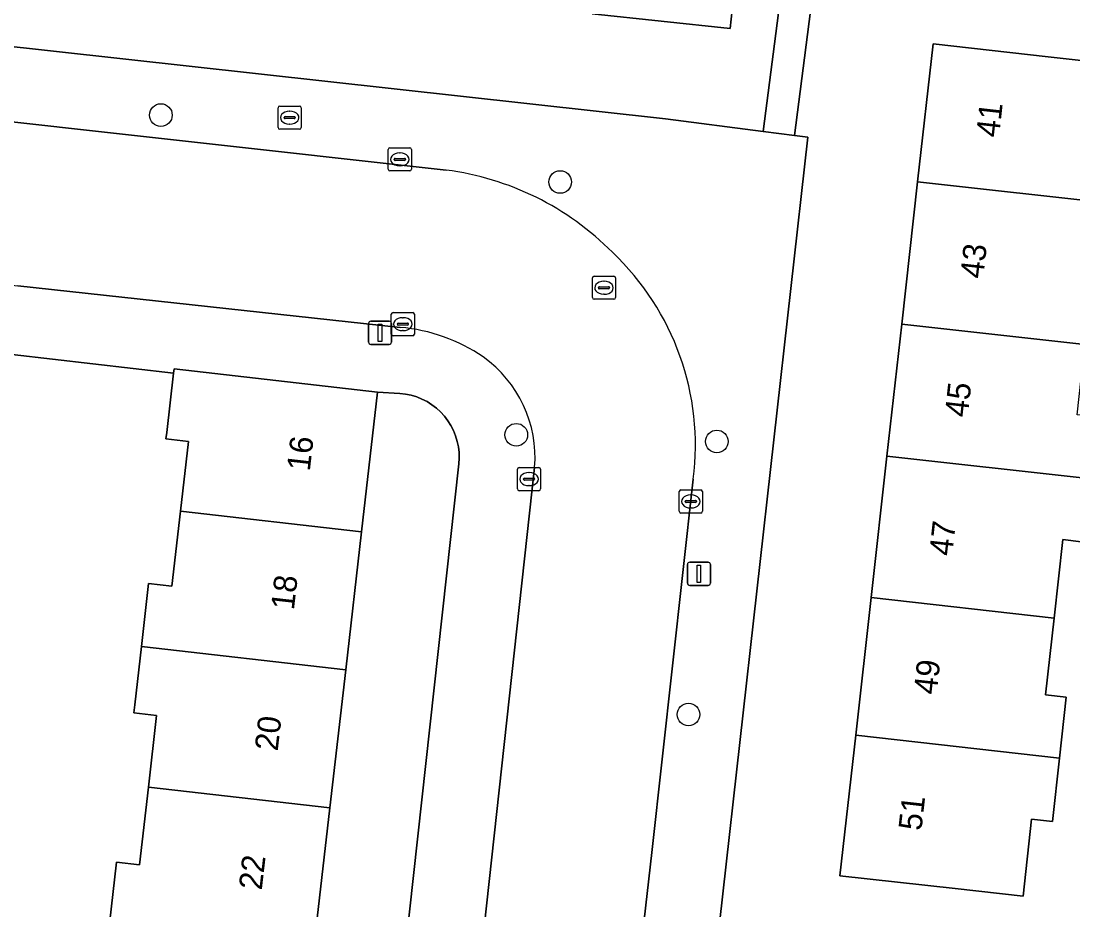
# Model space of a CAD drawing. Extents: x 162026 to 163502, y 387295 to 388169.
# Drawn here: x 162399.19 to 162444.62, y 387708.7 to 387747.09 of the extents above; entities that cross this region are included whole.
import ezdxf

# ---------------------------------------------------------------- set-up
doc = ezdxf.new("R2010")
doc.units = 0
for name, color, linetype in [('IMGEO_Boom', 7, 'Continuous'), ('IMGEO_Brandkraan', 7, 'Continuous'), ('IMGEO_Erf', 7, 'Continuous'), ('IMGEO_Kolk', 7, 'Continuous'), ('IMGEO_Lichtmast', 7, 'Continuous'), ('IMGEO_Pand', 7, 'Continuous'), ('IMGEO_Pand_nummerreeks', 7, 'Continuous'), ('IMGEO_Rijbaan_lokaal_open', 7, 'Continuous'), ('IMGEO_Rioolput', 7, 'Continuous'), ('IMGEO_Voetpad_open', 7, 'Continuous')]:
    doc.layers.add(name, color=color, linetype=linetype)

msp = doc.modelspace()

# ---------------------------------------------------------------- linework, layer by layer
at = {"layer": 'IMGEO_Boom'}
for centre in [(162405.228, 387743.028), (162422.469, 387740.137), (162420.578, 387729.22), (162429.235, 387728.932), (162428.012, 387717.135)]:
    msp.add_circle(centre, 0.489, dxfattribs=at)
at = {"layer": 'IMGEO_Brandkraan'}
for p, q in [((162410.289, 387742.49), (162410.289, 387743.342)), ((162410.364, 387743.416), (162411.216, 387743.416)), ((162410.777, 387743.196), (162410.802, 387743.196)), ((162411.29, 387743.342), (162411.29, 387742.49)), ((162410.548, 387742.91), (162410.548, 387742.922)), ((162410.986, 387742.873), (162410.588, 387742.873)), ((162410.591, 387742.959), (162410.989, 387742.959)), ((162411.032, 387742.922), (162411.032, 387742.91)), ((162411.216, 387742.416), (162410.364, 387742.416)), ((162410.8, 387742.636), (162410.775, 387742.636))]:
    msp.add_line(p, q, dxfattribs=at)
for points in [[(162410.289, 387742.49), (162410.289, 387743.342)], [(162410.364, 387743.416), (162411.216, 387743.416)], [(162411.29, 387743.342), (162411.29, 387742.49)], [(162411.216, 387742.416), (162410.364, 387742.416)]]:
    msp.add_lwpolyline(points, dxfattribs=at)
for centre, radius, start, end in [((162410.366, 387743.34), 0.0765, 91.552, 178.448), ((162410.366, 387743.34), 0.0765, 91.552, 178.448), ((162411.214, 387743.34), 0.0765, 1.552, 88.448), ((162411.214, 387743.34), 0.0765, 1.552, 88.448), ((162410.588, 387742.919), 0.0403, 85.8775, 175.7526), ((162410.585, 387742.909), 0.0366, 178.938, 274.7102), ((162410.989, 387742.916), 0.043, 264.8664, 352.4533), ((162410.993, 387742.921), 0.0386, 1.7309, 96.639), ((162410.366, 387742.492), 0.0765, 181.552, 268.448), ((162410.366, 387742.492), 0.0765, 181.552, 268.448), ((162411.214, 387742.492), 0.0765, 271.552, 358.448), ((162411.214, 387742.492), 0.0765, 271.552, 358.448)]:
    msp.add_arc(centre, radius, start, end, dxfattribs=at)
for centre, major_axis, ratio, start_param, end_param in [((162410.776, 387742.916), (-0.387, 0.002), 0.722429, 4.712389, 7.853982), ((162410.801, 387742.916), (-0.39, 0.002), 0.717154, 1.570796, 4.712389)]:
    msp.add_ellipse(centre, major_axis=major_axis, ratio=ratio, start_param=start_param, end_param=end_param, dxfattribs=at)
at = {"layer": 'IMGEO_Erf'}
for points in [[(162362.56, 387750), (162427.027, 387742.863), (162431.245, 387742.321), (162433.264, 387758.035)], [(162433.651, 387750.442), (162432.585, 387742.149), (162433.168, 387742.074), (162425.088, 387670.179)], [(162430.16, 387750), (162429.814, 387746.763), (162423.847, 387747.401)], [(162444.975, 387724.601), (162444.184, 387724.69), (162443.805, 387721.304), (162443.435, 387717.994), (162444.331, 387717.893), (162444.036, 387715.257), (162443.728, 387712.511), (162442.833, 387712.611), (162442.461, 387709.288), (162439.525, 387709.617), (162434.556, 387710.173), (162435.235, 387716.241), (162435.9, 387722.189), (162436.584, 387728.302), (162437.222, 387733.998), (162437.91, 387740.147), (162438.576, 387746.104), (162443.545, 387745.548), (162446.519, 387745.215)], [(162403.009, 387708.103), (162403.313, 387710.755), (162404.303, 387710.641), (162404.688, 387714.001), (162405.043, 387717.092), (162404.057, 387717.206), (162404.097, 387717.556), (162404.386, 387720.081), (162404.696, 387722.789), (162405.696, 387722.674), (162406.068, 387725.925), (162406.413, 387728.932), (162405.448, 387729.043), (162405.479, 387729.311), (162405.775, 387731.887), (162398.802, 387732.687)], [(162413.649, 387687.57), (162418.095, 387727.958), (162418.111, 387728.203), (162418.105, 387728.449), (162418.077, 387728.694), (162418.027, 387728.935), (162417.956, 387729.17), (162417.864, 387729.399), (162417.753, 387729.618), (162417.622, 387729.826), (162417.473, 387730.022), (162417.307, 387730.203), (162417.125, 387730.369), (162416.93, 387730.519), (162416.722, 387730.65), (162416.503, 387730.762), (162416.275, 387730.854), (162416.039, 387730.925), (162415.798, 387730.975), (162415.546, 387731.004), (162414.588, 387731.063), (162413.896, 387725.027), (162413.213, 387719.069), (162412.529, 387713.102), (162411.84, 387707.09)]]:
    msp.add_lwpolyline(points, dxfattribs=at)
at = {"layer": 'IMGEO_Kolk'}
for p, q in [((162415.046, 387740.687), (162415.046, 387741.539)), ((162415.121, 387741.613), (162415.973, 387741.613)), ((162415.534, 387741.393), (162415.559, 387741.393)), ((162416.047, 387741.539), (162416.047, 387740.687)), ((162415.305, 387741.107), (162415.305, 387741.119)), ((162415.743, 387741.07), (162415.345, 387741.07)), ((162415.348, 387741.156), (162415.746, 387741.156)), ((162415.789, 387741.119), (162415.789, 387741.107)), ((162415.973, 387740.613), (162415.121, 387740.613)), ((162415.557, 387740.833), (162415.532, 387740.833)), ((162415.179, 387733.571), (162415.179, 387734.423)), ((162415.254, 387734.497), (162416.106, 387734.497)), ((162415.667, 387734.277), (162415.692, 387734.277)), ((162416.18, 387734.423), (162416.18, 387733.571)), ((162415.438, 387733.991), (162415.438, 387734.003)), ((162415.876, 387733.954), (162415.478, 387733.954)), ((162415.481, 387734.04), (162415.879, 387734.04)), ((162415.69, 387733.717), (162415.665, 387733.717)), ((162415.922, 387734.003), (162415.922, 387733.991)), ((162416.106, 387733.497), (162415.254, 387733.497)), ((162420.627, 387726.878), (162420.627, 387727.73)), ((162420.702, 387727.804), (162421.554, 387727.804)), ((162421.628, 387727.73), (162421.628, 387726.878)), ((162420.886, 387727.298), (162420.886, 387727.31)), ((162421.324, 387727.261), (162420.926, 387727.261)), ((162420.929, 387727.347), (162421.327, 387727.347)), ((162421.115, 387727.584), (162421.14, 387727.584)), ((162421.37, 387727.31), (162421.37, 387727.298)), ((162421.554, 387726.804), (162420.702, 387726.804)), ((162421.138, 387727.024), (162421.113, 387727.024)), ((162427.689, 387726.839), (162428.541, 387726.839)), ((162427.614, 387725.913), (162427.614, 387726.765)), ((162427.873, 387726.333), (162427.873, 387726.345)), ((162427.916, 387726.382), (162428.314, 387726.382)), ((162428.102, 387726.619), (162428.127, 387726.619)), ((162428.357, 387726.345), (162428.357, 387726.333)), ((162428.615, 387726.765), (162428.615, 387725.913)), ((162428.311, 387726.296), (162427.913, 387726.296)), ((162428.125, 387726.059), (162428.1, 387726.059)), ((162428.541, 387725.839), (162427.689, 387725.839))]:
    msp.add_line(p, q, dxfattribs=at)
for points in [[(162415.046, 387740.687), (162415.046, 387741.539)], [(162415.121, 387741.613), (162415.973, 387741.613)], [(162416.047, 387741.539), (162416.047, 387740.687)], [(162415.973, 387740.613), (162415.121, 387740.613)], [(162415.179, 387733.571), (162415.179, 387734.423)], [(162415.254, 387734.497), (162416.106, 387734.497)], [(162416.18, 387734.423), (162416.18, 387733.571)], [(162416.106, 387733.497), (162415.254, 387733.497)], [(162420.627, 387726.878), (162420.627, 387727.73)], [(162420.702, 387727.804), (162421.554, 387727.804)], [(162421.628, 387727.73), (162421.628, 387726.878)], [(162421.554, 387726.804), (162420.702, 387726.804)], [(162427.689, 387726.839), (162428.541, 387726.839)], [(162427.614, 387725.913), (162427.614, 387726.765)], [(162428.615, 387726.765), (162428.615, 387725.913)], [(162428.541, 387725.839), (162427.689, 387725.839)]]:
    msp.add_lwpolyline(points, dxfattribs=at)
for centre, radius, start, end in [((162415.123, 387741.537), 0.0765, 91.552, 178.448), ((162415.123, 387741.537), 0.0765, 91.552, 178.448), ((162415.971, 387741.537), 0.0765, 1.552, 88.448), ((162415.971, 387741.537), 0.0765, 1.552, 88.448), ((162415.345, 387741.116), 0.0403, 85.8775, 175.7526), ((162415.342, 387741.106), 0.0366, 178.938, 274.7102), ((162415.746, 387741.113), 0.043, 264.8664, 352.4533), ((162415.75, 387741.118), 0.0386, 1.7309, 96.639), ((162415.123, 387740.689), 0.0765, 181.552, 268.448), ((162415.123, 387740.689), 0.0765, 181.552, 268.448), ((162415.971, 387740.689), 0.0765, 271.552, 358.448), ((162415.971, 387740.689), 0.0765, 271.552, 358.448), ((162415.256, 387734.421), 0.0765, 91.552, 178.448), ((162415.256, 387734.421), 0.0765, 91.552, 178.448), ((162416.104, 387734.421), 0.0765, 1.552, 88.448), ((162416.104, 387734.421), 0.0765, 1.552, 88.448), ((162415.478, 387734), 0.0403, 85.8775, 175.7526), ((162415.475, 387733.99), 0.0366, 178.938, 274.7102), ((162415.879, 387733.997), 0.043, 264.8664, 352.4533), ((162415.883, 387734.002), 0.0386, 1.7309, 96.639), ((162415.256, 387733.573), 0.0765, 181.552, 268.448), ((162415.256, 387733.573), 0.0765, 181.552, 268.448), ((162416.104, 387733.573), 0.0765, 271.552, 358.448), ((162416.104, 387733.573), 0.0765, 271.552, 358.448), ((162420.704, 387727.728), 0.0765, 91.552, 178.448), ((162420.704, 387727.728), 0.0765, 91.552, 178.448), ((162421.552, 387727.728), 0.0765, 1.552, 88.448), ((162421.552, 387727.728), 0.0765, 1.552, 88.448), ((162420.926, 387727.307), 0.0403, 85.8775, 175.7526), ((162420.923, 387727.297), 0.0366, 178.938, 274.7102), ((162421.327, 387727.304), 0.043, 264.8664, 352.4533), ((162421.331, 387727.309), 0.0386, 1.7309, 96.639), ((162420.704, 387726.88), 0.0765, 181.552, 268.448), ((162420.704, 387726.88), 0.0765, 181.552, 268.448), ((162421.552, 387726.88), 0.0765, 271.552, 358.448), ((162421.552, 387726.88), 0.0765, 271.552, 358.448), ((162427.691, 387726.763), 0.0765, 91.552, 178.448), ((162427.691, 387726.763), 0.0765, 91.552, 178.448), ((162428.539, 387726.763), 0.0765, 1.552, 88.448), ((162428.539, 387726.763), 0.0765, 1.552, 88.448), ((162427.913, 387726.342), 0.0403, 85.8775, 175.7526), ((162427.91, 387726.332), 0.0366, 178.938, 274.7102), ((162428.314, 387726.339), 0.043, 264.8664, 352.4533), ((162428.318, 387726.344), 0.0386, 1.7309, 96.639), ((162427.691, 387725.915), 0.0765, 181.552, 268.448), ((162427.691, 387725.915), 0.0765, 181.552, 268.448), ((162428.539, 387725.915), 0.0765, 271.552, 358.448), ((162428.539, 387725.915), 0.0765, 271.552, 358.448)]:
    msp.add_arc(centre, radius, start, end, dxfattribs=at)
for centre, major_axis, ratio, start_param, end_param in [((162415.533, 387741.113), (-0.387, 0.002), 0.722429, 4.712389, 7.853982), ((162415.558, 387741.113), (-0.39, 0.002), 0.717154, 1.570796, 4.712389), ((162415.666, 387733.997), (-0.387, 0.002), 0.722429, 4.712389, 7.853982), ((162415.691, 387733.997), (-0.39, 0.002), 0.717154, 1.570796, 4.712389), ((162421.114, 387727.304), (-0.387, 0.002), 0.722429, 4.712389, 7.853982), ((162421.139, 387727.304), (-0.39, 0.002), 0.717154, 1.570796, 4.712389), ((162428.101, 387726.339), (-0.387, 0.002), 0.722429, 4.712389, 7.853982), ((162428.126, 387726.339), (-0.39, 0.002), 0.717154, 1.570796, 4.712389)]:
    msp.add_ellipse(centre, major_axis=major_axis, ratio=ratio, start_param=start_param, end_param=end_param, dxfattribs=at)
at = {"layer": 'IMGEO_Lichtmast'}
for p, q in [((162414.297, 387734.125), (162415.087, 387734.125)), ((162415.087, 387734.125), (162414.297, 387734.125)), ((162414.197, 387733.225), (162414.197, 387734.025)), ((162414.197, 387734.025), (162414.197, 387733.225)), ((162415.187, 387734.025), (162415.187, 387733.225)), ((162415.187, 387733.225), (162415.187, 387734.025)), ((162415.087, 387733.125), (162414.297, 387733.125)), ((162414.297, 387733.125), (162415.087, 387733.125)), ((162427.968, 387722.814), (162427.968, 387723.614)), ((162427.968, 387723.614), (162427.968, 387722.814)), ((162428.068, 387723.714), (162428.858, 387723.714)), ((162428.858, 387723.714), (162428.068, 387723.714)), ((162428.958, 387723.614), (162428.958, 387722.814)), ((162428.958, 387722.814), (162428.958, 387723.614)), ((162428.858, 387722.714), (162428.068, 387722.714)), ((162428.068, 387722.714), (162428.858, 387722.714))]:
    msp.add_line(p, q, dxfattribs=at)
for points in [[(162414.617, 387734), (162414.767, 387734), (162414.767, 387733.25), (162414.617, 387733.25), (162414.617, 387734)], [(162428.388, 387723.589), (162428.538, 387723.589), (162428.538, 387722.839), (162428.388, 387722.839), (162428.388, 387723.589)]]:
    msp.add_lwpolyline(points, dxfattribs=at)
for centre, start, end in [((162414.297, 387734.025), 90, 180), ((162414.297, 387734.025), 90, 180), ((162415.087, 387734.025), 0, 90), ((162415.087, 387734.025), 360, 90), ((162414.297, 387733.225), 180, 270), ((162414.297, 387733.225), 180, 270), ((162415.087, 387733.225), 270, 0), ((162415.087, 387733.225), 270, 0), ((162428.068, 387723.614), 90, 180), ((162428.068, 387723.614), 90, 180), ((162428.858, 387723.614), 0, 90), ((162428.858, 387723.614), 360, 90), ((162428.068, 387722.814), 180, 270), ((162428.068, 387722.814), 180, 270), ((162428.858, 387722.814), 270, 0), ((162428.858, 387722.814), 270, 0)]:
    msp.add_arc(centre, 0.1, start, end, dxfattribs=at)
at = {"layer": 'IMGEO_Pand'}
for points in [[(162423.847, 387747.401), (162429.814, 387746.763), (162430.16, 387750), (162430.346, 387751.735), (162430.662, 387754.692), (162427.394, 387755.041), (162427.481, 387755.851), (162424.782, 387756.14), (162424.125, 387750)], [(162446.6, 387739.174), (162446.903, 387741.882), (162446.155, 387741.965), (162446.519, 387745.215), (162443.545, 387745.548), (162438.576, 387746.104), (162437.91, 387740.147)], [(162446.6, 387739.174), (162437.91, 387740.147), (162437.222, 387733.998), (162445.136, 387733.112), (162445.16, 387733.326), (162448.504, 387732.942), (162449.179, 387738.885)], [(162437.222, 387733.998), (162436.584, 387728.302), (162445.28, 387727.328), (162445.578, 387729.992), (162444.796, 387730.079), (162445.136, 387733.112)], [(162414.588, 387731.063), (162405.796, 387732.071), (162405.775, 387731.887), (162405.479, 387729.311), (162405.448, 387729.043), (162406.413, 387728.932), (162406.068, 387725.925), (162413.896, 387725.027)], [(162443.805, 387721.304), (162444.184, 387724.69), (162444.975, 387724.601), (162445.28, 387727.328), (162436.584, 387728.302), (162435.9, 387722.189)], [(162406.068, 387725.925), (162405.696, 387722.674), (162404.696, 387722.789), (162404.386, 387720.081), (162413.213, 387719.069), (162413.896, 387725.027)], [(162435.9, 387722.189), (162435.235, 387716.241), (162444.036, 387715.257), (162444.331, 387717.893), (162443.435, 387717.994), (162443.805, 387721.304)], [(162412.529, 387713.102), (162413.213, 387719.069), (162404.386, 387720.081), (162404.097, 387717.556), (162404.057, 387717.206), (162405.043, 387717.092), (162404.688, 387714.001)], [(162435.235, 387716.241), (162434.556, 387710.173), (162439.525, 387709.617), (162442.461, 387709.288), (162442.833, 387712.611), (162443.728, 387712.511), (162444.036, 387715.257)], [(162411.84, 387707.09), (162412.529, 387713.102), (162404.688, 387714.001), (162404.303, 387710.641), (162403.313, 387710.755), (162403.009, 387708.103)]]:
    msp.add_lwpolyline(points, close=True, dxfattribs=at)
at = {"layer": 'IMGEO_Rijbaan_lokaal_open'}
for points in [[(162417.549, 387740.654), (162395.142, 387743.141), (162394.357, 387736.172), (162399.048, 387735.657), (162415.566, 387733.856)], [(162421.368, 387727.812), (162416.894, 387687.047)], [(162423.42, 387684.486), (162425.761, 387705.232), (162426.424, 387711.183), (162428.221, 387727.308)]]:
    msp.add_lwpolyline(points, dxfattribs=at)
for centre, radius, start, end in [((162415.949, 387728.392), 12.366, 44.7649, 82.5656), ((162416.832, 387728.765), 11.482, 352.7084, 46.5458), ((162414.933, 387726.416), 7.467, 55.6543, 85.1394), ((162416.07, 387728.245), 5.316, 355.3227, 54.6414)]:
    msp.add_arc(centre, radius, start, end, dxfattribs=at)
at = {"layer": 'IMGEO_Rioolput'}
for p, q in [((162423.863, 387735.144), (162423.863, 387735.996)), ((162423.938, 387736.07), (162424.79, 387736.07)), ((162424.864, 387735.996), (162424.864, 387735.144)), ((162424.122, 387735.564), (162424.122, 387735.576)), ((162424.56, 387735.527), (162424.162, 387735.527)), ((162424.165, 387735.613), (162424.563, 387735.613)), ((162424.351, 387735.85), (162424.376, 387735.85)), ((162424.606, 387735.576), (162424.606, 387735.564)), ((162424.79, 387735.07), (162423.938, 387735.07)), ((162424.374, 387735.29), (162424.349, 387735.29))]:
    msp.add_line(p, q, dxfattribs=at)
for points in [[(162423.863, 387735.144), (162423.863, 387735.996)], [(162423.938, 387736.07), (162424.79, 387736.07)], [(162424.864, 387735.996), (162424.864, 387735.144)], [(162424.79, 387735.07), (162423.938, 387735.07)]]:
    msp.add_lwpolyline(points, dxfattribs=at)
for centre, radius, start, end in [((162423.94, 387735.994), 0.0765, 91.552, 178.448), ((162423.94, 387735.994), 0.0765, 91.552, 178.448), ((162424.788, 387735.994), 0.0765, 1.552, 88.448), ((162424.788, 387735.994), 0.0765, 1.552, 88.448), ((162424.162, 387735.573), 0.0403, 85.8775, 175.7526), ((162424.159, 387735.563), 0.0366, 178.938, 274.7102), ((162424.563, 387735.57), 0.043, 264.8664, 352.4533), ((162424.567, 387735.575), 0.0386, 1.7309, 96.639), ((162423.94, 387735.146), 0.0765, 181.552, 268.448), ((162423.94, 387735.146), 0.0765, 181.552, 268.448), ((162424.788, 387735.146), 0.0765, 271.552, 358.448), ((162424.788, 387735.146), 0.0765, 271.552, 358.448)]:
    msp.add_arc(centre, radius, start, end, dxfattribs=at)
for centre, major_axis, ratio, start_param, end_param in [((162424.35, 387735.57), (-0.387, 0.002), 0.722429, 4.712389, 7.853982), ((162424.375, 387735.57), (-0.39, 0.002), 0.717154, 1.570796, 4.712389)]:
    msp.add_ellipse(centre, major_axis=major_axis, ratio=ratio, start_param=start_param, end_param=end_param, dxfattribs=at)
at = {"layer": 'IMGEO_Voetpad_open'}
for points in [[(162433.264, 387758.035), (162431.245, 387742.321), (162432.585, 387742.149), (162433.651, 387750.442)], [(162354.825, 387677.763), (162355.06, 387677.88), (162355.305, 387677.976), (162355.557, 387678.05), (162355.815, 387678.1), (162356.076, 387678.128), (162356.339, 387678.132), (162356.601, 387678.112), (162386.507, 387674.529), (162391.724, 387673.904), (162393.448, 387673.699), (162419.619, 387670.747), (162425.088, 387670.179), (162433.168, 387742.074), (162432.585, 387742.149), (162431.245, 387742.321), (162427.027, 387742.863), (162362.56, 387750)], [(162373.324, 387745.562), (162395.142, 387743.141), (162417.549, 387740.654)], [(162415.566, 387733.856), (162399.048, 387735.657)], [(162398.802, 387732.687), (162405.775, 387731.887), (162405.796, 387732.071), (162414.588, 387731.063), (162415.546, 387731.004), (162415.798, 387730.975), (162416.039, 387730.925), (162416.275, 387730.854), (162416.503, 387730.762), (162416.722, 387730.65), (162416.93, 387730.519), (162417.125, 387730.369), (162417.307, 387730.203), (162417.473, 387730.022), (162417.622, 387729.826), (162417.753, 387729.618), (162417.864, 387729.399), (162417.956, 387729.17), (162418.027, 387728.935), (162418.077, 387728.694), (162418.105, 387728.449), (162418.111, 387728.203), (162418.095, 387727.958), (162413.649, 387687.57)], [(162416.894, 387687.047), (162421.368, 387727.812)], [(162428.221, 387727.308), (162426.424, 387711.183), (162425.761, 387705.232), (162423.42, 387684.486)]]:
    msp.add_lwpolyline(points, dxfattribs=at)
for centre, radius, start, end in [((162415.949, 387728.392), 12.366, 44.7649, 82.5656), ((162416.832, 387728.765), 11.482, 352.7084, 46.5458), ((162414.933, 387726.416), 7.467, 55.6543, 85.1394), ((162416.07, 387728.245), 5.316, 355.3227, 54.6414)]:
    msp.add_arc(centre, radius, start, end, dxfattribs=at)

# ---------------------------------------------------------------- texts
at = {"layer": 'IMGEO_Pand_nummerreeks'}
for s, rotation, p in [('41', 83.6162, (162441.421, 387742.036)), ('43', 83.6175, (162440.738, 387735.936)), ('45', 83.6162, (162440.068, 387729.947)), ('16', 83.4628, (162411.657, 387727.62)), ('47', 83.6162, (162439.398, 387723.959)), ('18', 83.4618, (162410.97, 387721.623)), ('49', 83.6162, (162438.728, 387717.97)), ('20', 83.4618, (162410.271, 387715.534)), ('51', 83.6162, (162438.071, 387712.094)), ('22', 83.4618, (162409.583, 387709.529))]:
    msp.add_text(s, height=1, rotation=rotation, dxfattribs=at).set_placement(p)

doc.saveas('drawing.dxf')
